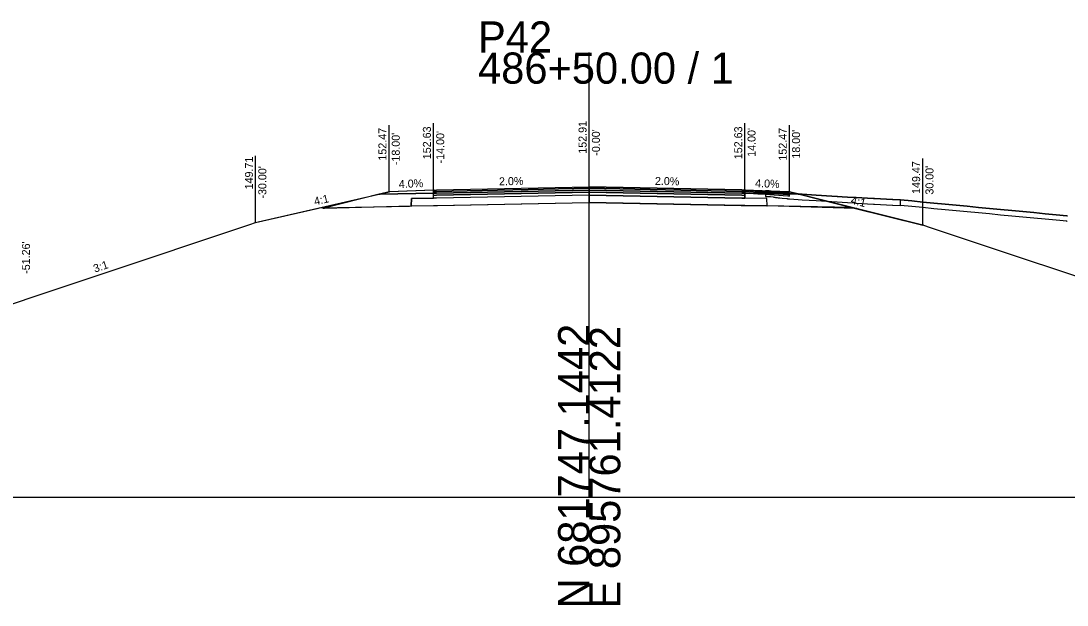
# Model space of a CAD drawing. Extents: x -26 to 4403, y -13 to 9578.
# Drawn here: x 3198.9 to 3293, y 8490.3 to 8542.8 of the extents above; entities that cross this region are included whole.
import ezdxf

# ---------------------------------------------------------------- set-up
doc = ezdxf.new("R2010")
doc.units = 0
for name, color, linetype in [('ASPHALT_19MM1', 7, 'Continuous'), ('ASPHALT_19MM2', 7, 'Continuous'), ('ASPHALT_9_5MM1', 7, 'Continuous'), ('CONST_LV3', 7, 'Continuous'), ('CONST_PROF_LV1', 7, 'Continuous'), ('Default', 7, 'Continuous'), ('DTM CONTOURS_MAJOR', 7, 'Continuous'), ('DTM_P_FINISHED_GRADE', 7, 'Continuous'), ('DTM_X_BOUNDARY', 7, 'Continuous'), ('XS_CELL', 7, 'Continuous'), ('XS_P_ASPHALT', 7, 'Continuous'), ('XS_P_CRUSHED_STONE', 7, 'Continuous'), ('XS_P_DR_ASPHALT', 7, 'Continuous'), ('XS_P_DR_ASPHALT_B', 7, 'Continuous'), ('XS_P_DR_GRAVEL', 7, 'Continuous'), ('XS_P_GROUND', 7, 'Continuous'), ('XS_P_SHOULDER', 7, 'Continuous'), ('XS_P_SUBGRADE_GRANULAR', 7, 'Continuous'), ('XS_P_TX_CLEARZONE', 7, 'Continuous'), ('XS_P_TX_FS_BS', 7, 'Continuous')]:
    doc.layers.add(name, color=color, linetype=linetype)

msp = doc.modelspace()

# ---------------------------------------------------------------- linework, layer by layer
at = {"layer": 'ASPHALT_19MM1'}
for points in [[(3236.272, 8527.349), (3250, 8527.623), (3250, 8527.439), (3250, 8527.436), (3236.272, 8527.161), (3236, 8527.156), (3236, 8527.159), (3236, 8527.343), (3236.272, 8527.349)], [(3263.728, 8527.349), (3250, 8527.623), (3250, 8527.439), (3250, 8527.436), (3263.728, 8527.161), (3264, 8527.156), (3264, 8527.159), (3264, 8527.343), (3263.728, 8527.349)]]:
    msp.add_lwpolyline(points, dxfattribs=at)
at = {"layer": 'ASPHALT_19MM2'}
for points in [[(3236.272, 8527.161), (3250, 8527.436), (3250, 8527.191), (3250, 8527.186), (3236.272, 8526.911), (3236, 8526.906), (3236, 8526.911), (3236, 8527.156), (3236.272, 8527.161)], [(3263.728, 8527.161), (3250, 8527.436), (3250, 8527.191), (3250, 8527.186), (3263.728, 8526.911), (3264, 8526.906), (3264, 8526.911), (3264, 8527.156), (3263.728, 8527.161)]]:
    msp.add_lwpolyline(points, dxfattribs=at)
at = {"layer": 'ASPHALT_9_5MM1'}
for points in [[(3236.272, 8527.64), (3250, 8527.915), (3250, 8527.792), (3250, 8527.79), (3236.272, 8527.515), (3236, 8527.51), (3236, 8527.512), (3236, 8527.635), (3236.272, 8527.64)], [(3263.728, 8527.64), (3250, 8527.915), (3250, 8527.792), (3250, 8527.79), (3263.728, 8527.515), (3264, 8527.51), (3264, 8527.512), (3264, 8527.635), (3263.728, 8527.64)]]:
    msp.add_lwpolyline(points, dxfattribs=at)
at = {"layer": 'CONST_LV3'}
for points in [[(3264, 8527.635), (3264.894, 8527.568), (3266.022, 8527.483), (3266.505, 8527.447), (3267.165, 8527.398), (3268.796, 8527.287), (3269.146, 8527.262), (3272.002, 8527.082), (3272.167, 8527.075), (3272.333, 8527.068), (3273.787, 8526.972), (3273.879, 8526.968), (3273.97, 8526.965), (3275.558, 8526.869), (3275.592, 8526.867), (3275.626, 8526.866), (3275.66, 8526.865), (3277.289, 8526.777), (3277.292, 8526.776), (3277.295, 8526.776), (3278, 8526.742), (3278, 8526.742), (3279, 8526.647), (3280, 8526.552), (3281, 8526.457), (3282, 8526.362), (3283, 8526.267), (3284, 8526.172), (3285, 8526.077), (3286, 8525.982), (3287, 8525.887), (3288, 8525.792), (3289, 8525.697), (3290, 8525.602), (3291, 8525.507), (3292, 8525.412), (3292.941, 8525.322), (3292.961, 8525.317), (3293, 8525.309)], [(3220, 8524.706), (3225.642, 8526.007), (3225.756, 8526.034)], [(3273.72, 8526.045), (3280, 8524.475)]]:
    msp.add_lwpolyline(points, dxfattribs=at)
at = {"layer": 'Default'}
for points in [[(3236.272, 8527.515), (3250, 8527.79), (3250, 8527.626), (3250, 8527.623), (3236.272, 8527.349), (3236, 8527.343), (3236, 8527.346), (3236, 8527.51), (3236.272, 8527.515)], [(3263.728, 8527.515), (3250, 8527.79), (3250, 8527.626), (3250, 8527.623), (3263.728, 8527.349), (3264, 8527.343), (3264, 8527.346), (3264, 8527.51), (3263.728, 8527.515)]]:
    msp.add_lwpolyline(points, dxfattribs=at)
at = {"layer": 'DTM_P_FINISHED_GRADE'}
for points in [[(3264, 8527.635), (3265.152, 8527.548), (3265.348, 8527.534), (3265.831, 8527.498), (3267.871, 8527.349), (3267.897, 8527.348), (3268, 8527.341)], [(3265.856, 8527.561), (3265.904, 8527.559), (3266.022, 8527.554), (3266.107, 8527.551), (3266.117, 8527.55), (3266.133, 8527.55), (3266.177, 8527.548), (3266.24, 8527.545), (3266.25, 8527.545), (3266.29, 8527.543), (3266.528, 8527.514), (3266.59, 8527.49), (3266.658, 8527.483), (3266.66, 8527.483), (3266.695, 8527.479), (3266.759, 8527.472), (3266.856, 8527.459), (3266.903, 8527.454), (3266.983, 8527.445), (3267.028, 8527.44), (3267.107, 8527.431), (3267.151, 8527.426), (3267.339, 8527.408), (3267.776, 8527.359), (3267.787, 8527.358), (3267.79, 8527.358), (3267.799, 8527.357), (3267.82, 8527.354), (3267.836, 8527.353), (3267.871, 8527.349), (3267.897, 8527.348), (3268, 8527.341), (3268.796, 8527.287), (3269.146, 8527.262), (3270.398, 8527.182), (3273.226, 8527.003), (3273.879, 8526.968), (3273.97, 8526.965), (3275.558, 8526.869), (3275.592, 8526.867), (3275.626, 8526.866), (3275.66, 8526.865), (3277.289, 8526.777), (3277.292, 8526.776), (3277.295, 8526.776), (3278, 8526.742), (3278, 8526.742), (3279, 8526.647), (3280, 8526.552), (3281, 8526.457), (3282, 8526.362), (3283, 8526.267), (3284, 8526.172), (3285, 8526.077), (3286, 8525.982), (3287, 8525.887), (3288, 8525.792), (3289, 8525.697), (3290, 8525.602), (3291, 8525.507), (3292, 8525.412), (3292.941, 8525.322), (3292.961, 8525.317), (3293, 8525.309)]]:
    msp.add_lwpolyline(points, dxfattribs=at)
at = {"layer": 'XS_CELL'}
for p, q in [((3250, 8500), (3250, 8540)), ((3000, 8500), (3250, 8500)), ((3250, 8500), (3400, 8500))]:
    msp.add_line(p, q, dxfattribs=at)
at = {"layer": 'XS_P_ASPHALT'}
msp.add_lwpolyline([(3236.272, 8527.64), (3250, 8527.915), (3263.728, 8527.64), (3264, 8527.635), (3264, 8526.92), (3264, 8526.906), (3263.728, 8526.911), (3250, 8527.186), (3236.272, 8526.911), (3236, 8526.906), (3236, 8526.92), (3236, 8527.635), (3236.272, 8527.64)], dxfattribs=at)
at = {"layer": 'XS_P_CRUSHED_STONE'}
for points in [[(3232.078, 8527.478), (3232, 8527.475), (3231.123, 8527.256), (3231.106, 8527.251), (3231.201, 8527.253), (3236, 8527.343), (3236, 8527.349), (3236, 8527.635), (3232.078, 8527.478)], [(3234.04, 8526.2), (3236.078, 8526.241), (3236.349, 8526.246), (3250, 8526.519), (3250, 8526.532), (3250, 8527.186), (3236.272, 8526.911), (3236, 8526.906), (3234.053, 8526.879), (3234.014, 8526.878), (3234, 8526.212), (3234, 8526.199), (3234.04, 8526.2)], [(3265.96, 8526.2), (3266, 8526.199), (3266, 8526.212), (3265.986, 8526.878), (3265.947, 8526.879), (3264, 8526.906), (3263.728, 8526.911), (3250, 8527.186), (3250, 8526.532), (3250, 8526.519), (3263.651, 8526.246), (3263.922, 8526.241), (3265.96, 8526.2)], [(3267.922, 8527.478), (3264, 8527.635), (3264, 8527.349), (3264, 8527.343), (3268.799, 8527.253), (3268.894, 8527.251), (3268.877, 8527.256), (3268, 8527.475), (3267.922, 8527.478)]]:
    msp.add_lwpolyline(points, dxfattribs=at)
at = {"layer": 'XS_P_DR_ASPHALT'}
msp.add_lwpolyline([(3264, 8527.635), (3264, 8527.51), (3265.152, 8527.423), (3265.348, 8527.409), (3265.831, 8527.373), (3267.871, 8527.224), (3267.897, 8527.223), (3268, 8527.216), (3268, 8527.341), (3267.897, 8527.348), (3267.871, 8527.349), (3265.831, 8527.498), (3265.348, 8527.534), (3265.152, 8527.548), (3264, 8527.635)], dxfattribs=at)
at = {"layer": 'XS_P_DR_ASPHALT_B'}
msp.add_lwpolyline([(3264, 8527.51), (3264, 8527.385), (3265.152, 8527.298), (3265.348, 8527.284), (3265.831, 8527.248), (3267.871, 8527.099), (3267.897, 8527.098), (3268, 8527.091), (3268, 8527.216), (3267.897, 8527.223), (3267.871, 8527.224), (3265.831, 8527.373), (3265.348, 8527.409), (3265.152, 8527.423), (3264, 8527.51)], dxfattribs=at)
at = {"layer": 'XS_P_DR_GRAVEL'}
for points in [[(3265.856, 8527.561), (3265.856, 8527.061), (3265.904, 8527.059), (3266.022, 8527.054), (3266.107, 8527.051), (3266.117, 8527.05), (3266.133, 8527.05), (3266.177, 8527.048), (3266.24, 8527.045), (3266.25, 8527.045), (3266.29, 8527.043), (3266.528, 8527.014), (3266.59, 8526.99), (3266.658, 8526.983), (3266.66, 8526.983), (3266.695, 8526.979), (3266.759, 8526.972), (3266.856, 8526.959), (3266.903, 8526.954), (3266.983, 8526.945), (3267.028, 8526.94), (3267.107, 8526.931), (3267.151, 8526.926), (3267.339, 8526.908), (3267.776, 8526.859), (3267.787, 8526.858), (3267.79, 8526.858), (3267.799, 8526.857), (3267.82, 8526.854), (3267.836, 8526.853), (3267.871, 8526.849), (3267.897, 8526.848), (3268, 8526.841), (3268, 8526.841), (3268, 8526.841), (3268.796, 8526.787), (3269.146, 8526.762), (3270.398, 8526.682), (3273.226, 8526.503), (3273.879, 8526.468), (3273.97, 8526.465), (3275.558, 8526.369), (3275.592, 8526.367), (3275.626, 8526.366), (3275.66, 8526.365), (3277.289, 8526.277), (3277.292, 8526.276), (3277.295, 8526.276), (3278, 8526.242), (3278, 8526.742), (3277.295, 8526.776), (3277.292, 8526.776), (3277.289, 8526.777), (3275.66, 8526.865), (3275.626, 8526.866), (3275.592, 8526.867), (3275.558, 8526.869), (3273.97, 8526.965), (3273.879, 8526.968), (3273.226, 8527.003), (3270.398, 8527.182), (3269.146, 8527.262), (3268.796, 8527.287), (3268, 8527.341), (3268, 8527.341), (3268, 8527.341), (3267.897, 8527.348), (3267.871, 8527.349), (3267.836, 8527.353), (3267.82, 8527.354), (3267.799, 8527.357), (3267.79, 8527.358), (3267.787, 8527.358), (3267.776, 8527.359), (3267.339, 8527.408), (3267.151, 8527.426), (3267.107, 8527.431), (3267.028, 8527.44), (3266.983, 8527.445), (3266.903, 8527.454), (3266.856, 8527.459), (3266.759, 8527.472), (3266.695, 8527.479), (3266.66, 8527.483), (3266.658, 8527.483), (3266.59, 8527.49), (3266.528, 8527.514), (3266.29, 8527.543), (3266.25, 8527.545), (3266.24, 8527.545), (3266.177, 8527.548), (3266.133, 8527.55), (3266.117, 8527.55), (3266.107, 8527.551), (3266.022, 8527.554), (3265.904, 8527.559), (3265.856, 8527.561)], [(3278, 8526.242), (3278, 8526.242), (3278, 8526.242)], [(3292.976, 8524.814), (3292.961, 8524.817), (3292.961, 8524.817), (3292.941, 8524.822), (3292.941, 8524.822), (3292, 8524.912), (3292, 8524.912), (3291, 8525.007), (3291, 8525.007), (3290, 8525.102), (3290, 8525.102), (3289, 8525.197), (3289, 8525.197), (3288, 8525.292), (3288, 8525.292), (3287, 8525.387), (3287, 8525.387), (3286, 8525.482), (3286, 8525.482), (3285, 8525.577), (3285, 8525.577), (3284, 8525.672), (3284, 8525.672), (3283, 8525.767), (3283, 8525.767), (3282, 8525.862), (3282, 8525.862), (3281, 8525.957), (3281, 8525.957), (3280, 8526.052), (3280, 8526.052), (3280, 8526.052), (3279, 8526.147), (3279, 8526.147), (3278, 8526.242)]]:
    msp.add_lwpolyline(points, dxfattribs=at)
at = {"layer": 'XS_P_GROUND'}
for points in [[(3192.437, 8515.52), (3219.467, 8524.528), (3220, 8524.706), (3220.234, 8524.761), (3232, 8527.475)], [(3320.13, 8511.099), (3280.781, 8524.215), (3280, 8524.475), (3279.766, 8524.533), (3268, 8527.475)], [(3278, 8526.742), (3278, 8526.742), (3278, 8526.742)], [(3292.976, 8525.314), (3292.961, 8525.317), (3292.941, 8525.322), (3292.941, 8525.322), (3292, 8525.412), (3292, 8525.412), (3291, 8525.507), (3291, 8525.507), (3290, 8525.602), (3290, 8525.602), (3289, 8525.697), (3289, 8525.697), (3288, 8525.792), (3288, 8525.792), (3287, 8525.887), (3287, 8525.887), (3286, 8525.982), (3286, 8525.982), (3285, 8526.077), (3285, 8526.077), (3284, 8526.172), (3284, 8526.172), (3283, 8526.267), (3283, 8526.267), (3282, 8526.362), (3282, 8526.362), (3281, 8526.457), (3281, 8526.457), (3280, 8526.552), (3280, 8526.552), (3279, 8526.647), (3279, 8526.647), (3278, 8526.742)]]:
    msp.add_lwpolyline(points, dxfattribs=at)
at = {"layer": 'XS_P_SHOULDER'}
for points in [[(3236, 8527.635), (3232, 8527.475)], [(3264, 8527.635), (3268, 8527.475)]]:
    msp.add_lwpolyline(points, dxfattribs=at)
at = {"layer": 'XS_P_SUBGRADE_GRANULAR'}
for points in [[(3236, 8526.914), (3236, 8527.343), (3231.201, 8527.253), (3231.106, 8527.251), (3226.15, 8526.012), (3226.052, 8525.988), (3226.206, 8525.992), (3234, 8526.199), (3234, 8526.212), (3234.014, 8526.878), (3234.053, 8526.879), (3236, 8526.906), (3236, 8526.914)], [(3264, 8526.914), (3264, 8527.343), (3268.799, 8527.253), (3268.894, 8527.251), (3273.959, 8525.985), (3274.059, 8525.96), (3273.903, 8525.965), (3266, 8526.199), (3266, 8526.212), (3265.986, 8526.878), (3265.947, 8526.879), (3264, 8526.906), (3264, 8526.914)], [(3225.756, 8526.034), (3233.842, 8526.196), (3234, 8526.199), (3234.039, 8526.2), (3236, 8526.239)], [(3236, 8526.239), (3236.272, 8526.245), (3250, 8526.519)], [(3264, 8526.239), (3263.728, 8526.245), (3250, 8526.519)], [(3273.72, 8526.045), (3273.57, 8526.048), (3266, 8526.199), (3265.961, 8526.2), (3264, 8526.239)]]:
    msp.add_lwpolyline(points, dxfattribs=at)
at = {"layer": 'XS_P_TX_CLEARZONE'}
for p, q in [((3250, 8527.915), (3250, 8533.915)), ((3232, 8527.475), (3232, 8533.475)), ((3236, 8527.635), (3236, 8533.635)), ((3264, 8527.635), (3264, 8533.635)), ((3268, 8527.475), (3268, 8533.475)), ((3220, 8524.706), (3220, 8530.706)), ((3220, 8524.706), (3220, 8530.706)), ((3280, 8524.475), (3280, 8530.475)), ((3280, 8524.475), (3280, 8530.475))]:
    msp.add_line(p, q, dxfattribs=at)

# ---------------------------------------------------------------- texts
at = {"layer": 'CONST_PROF_LV1'}
for p in [(3219.961, 8524.646), (3279.961, 8524.415)]:
    msp.add_text('X', height=0.12, dxfattribs=at).set_placement(p)
at = {"layer": 'Default'}
for p in [(3219.961, 8524.646), (3279.961, 8524.415)]:
    msp.add_text('X', height=0.12, dxfattribs=at).set_placement(p)
at = {"layer": 'DTM CONTOURS_MAJOR'}
for p in [(3235.961, 8527.575), (3249.961, 8527.855), (3263.961, 8527.575)]:
    msp.add_text('X', height=0.12, dxfattribs=at).set_placement(p)
at = {"layer": 'DTM_X_BOUNDARY'}
for p in [(3231.961, 8527.415), (3267.961, 8527.415)]:
    msp.add_text('X', height=0.12, dxfattribs=at).set_placement(p)
at = {"layer": 'XS_CELL'}
for s, p in [('P42', (3240, 8540)), ('486+50.00 / 1', (3240, 8537.2))]:
    msp.add_text(s, height=2.8, dxfattribs=at).set_placement(p)
for s, p in [('N 681747.1442', (3250, 8490)), ('E 895761.4122', (3252.8, 8490))]:
    msp.add_text(s, height=2.8, rotation=90, dxfattribs=at).set_placement(p)
at = {"layer": 'XS_P_TX_CLEARZONE'}
for s, p in [('152.91', (3249.76, 8530.9)), ('152.47', (3231.76, 8530.279)), ("-18.00'", (3232.96, 8529.871)), ('152.63', (3235.76, 8530.405)), ("-14.00'", (3236.96, 8530.031)), ("-0.00'", (3250.96, 8530.719)), ('152.63', (3263.76, 8530.405)), ("14.00'", (3264.96, 8530.62)), ('152.47', (3267.76, 8530.279)), ("18.00'", (3268.96, 8530.46)), ('149.71', (3219.76, 8527.692)), ('149.71', (3219.76, 8527.692)), ('149.47', (3279.76, 8527.279)), ('149.47', (3279.76, 8527.279)), ("-30.00'", (3220.96, 8526.864)), ("-30.00'", (3220.96, 8526.864)), ("30.00'", (3280.96, 8527.222)), ("30.00'", (3280.96, 8527.222)), ("-51.26'", (3199.702, 8520.096))]:
    msp.add_text(s, height=0.72, rotation=90, dxfattribs=at).set_placement(p)
at = {"layer": 'XS_P_TX_FS_BS'}
for s, rotation, p in [('4.0%', 2.29061, (3232.887, 8527.811)), ('2.0%', 1.14576, (3241.892, 8528.053)), ('2.0%', 358.85424, (3255.904, 8528.097)), ('4.0%', 357.70939, (3264.911, 8527.899)), ('4:1', 12.99192, (3225.336, 8526.245)), ('4:1', 345.96376, (3273.479, 8526.414)), ('3:1', 18.43323, (3205.543, 8520.204))]:
    msp.add_text(s, height=0.72, rotation=rotation, dxfattribs=at).set_placement(p)

doc.saveas('drawing.dxf')
